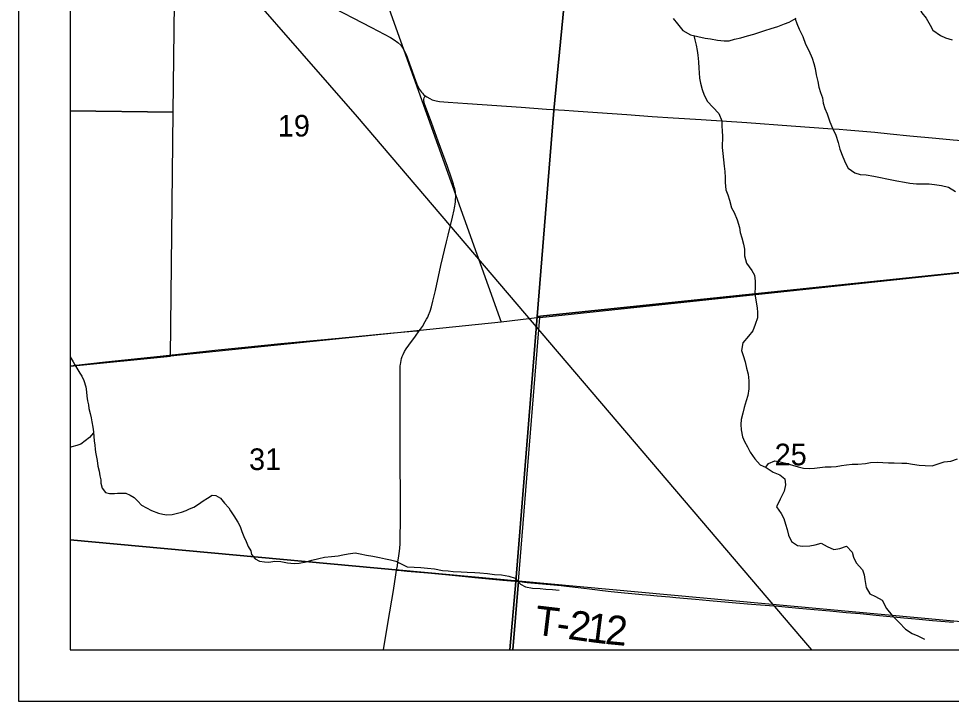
# Model space of a CAD drawing. Extents: x 0 to 34, y -5.4 to 22.
# Drawn here: x 2 to 3.809, y 14 to 15.324 of the extents above; entities that cross this region are included whole.
import ezdxf

# ---------------------------------------------------------------- set-up
doc = ezdxf.new("R2010")
doc.units = 0
for name, color, linetype in [('Default', 7, 'Continuous'), ('GM_X_County_Road', 7, 'Continuous'), ('GM_X_Minor_River', 7, 'Continuous'), ('GM_X_Rail_Line', 7, 'Continuous'), ('GM_X_Section', 7, 'Continuous'), ('GM_X_Section_Text', 7, 'Continuous'), ('GM_X_Township_Road', 7, 'Continuous'), ('GM_X_Township_Road_Text', 7, 'Continuous'), ('SH_Data', 7, 'Continuous')]:
    doc.layers.add(name, color=color, linetype=linetype)

msp = doc.modelspace()

# ---------------------------------------------------------------- linework, layer by layer
at = {"layer": 'Default'}
for points in [[(2.1, 16.1508), (2.1, 15.1447), (2.2999, 15.1427), (2.3117, 16.1481)], [(2.1, 15.1447), (2.1, 14.6497), (2.2946, 14.6693), (2.2999, 15.1427)], [(2.1, 14.6497), (2.1, 14.3134), (2.9696, 14.2333), (3.0111, 14.744), (2.936, 14.7352), (2.2946, 14.6693)], [(2.1, 14.3134), (2.1, 14.1), (2.9585, 14.1), (2.9696, 14.2333)], [(2.9585, 14.1), (3.9718, 14.1), (3.9753, 14.1377), (3.9754, 14.1403), (2.9696, 14.2333)]]:
    msp.add_lwpolyline(points, close=True, dxfattribs=at)
at = {"layer": 'GM_X_County_Road'}
for points in [[(2.5943, 15.3533), (2.6843, 15.3064), (2.7211, 15.2873), (2.7285, 15.2828), (2.7356, 15.2775), (2.741, 15.2721), (2.745, 15.2668), (2.7485, 15.2607), (2.7514, 15.2544), (2.7697, 15.2036), (2.7722, 15.1969), (2.7747, 15.1916), (2.7774, 15.1863), (2.7811, 15.1811), (2.7831, 15.179), (2.7853, 15.1769), (2.7887, 15.1742), (2.7919, 15.172), (2.7974, 15.1687), (2.802, 15.1665), (2.8046, 15.1656), (2.8073, 15.1648), (2.8101, 15.1642), (2.8128, 15.1638), (2.8163, 15.1633), (2.8331, 15.1616), (2.8703, 15.1589), (2.9744, 15.1519), (3.024, 15.1485), (3.0588, 15.1461)], [(3.0588, 15.1461), (3.0761, 15.1449), (3.1226, 15.1417), (3.1796, 15.1377), (3.2286, 15.1343), (3.2695, 15.1315), (3.3241, 15.1279), (3.4127, 15.1221), (3.4983, 15.1162), (3.5785, 15.1102), (3.5913, 15.1092), (3.6065, 15.1081), (3.6608, 15.1033), (3.6903, 15.1005), (3.7286, 15.0967), (3.7787, 15.0919), (3.8127, 15.0888), (3.8542, 15.0853), (3.892, 15.0828), (3.9472, 15.0791), (3.9927, 15.0764), (4.065, 15.0719), (4.0712, 15.0715)]]:
    msp.add_lwpolyline(points, dxfattribs=at)
at = {"layer": 'GM_X_Minor_River'}
for points in [[(3.6771, 15.4213), (3.6791, 15.4103), (3.6831, 15.3981), (3.698, 15.3891), (3.7082, 15.3848), (3.7183, 15.3782), (3.7292, 15.3708), (3.7395, 15.3566), (3.7447, 15.347), (3.7516, 15.3348), (3.7602, 15.3247), (3.7683, 15.311), (3.773, 15.3014), (3.788, 15.2909), (3.7978, 15.2866), (3.8109, 15.2825)], [(3.2697, 15.324), (3.2779, 15.3136), (3.2883, 15.3009), (3.3029, 15.2923), (3.3172, 15.2891), (3.3319, 15.2861), (3.3421, 15.2848), (3.3553, 15.2823), (3.3685, 15.2806), (3.3784, 15.2808), (3.3882, 15.2837), (3.4008, 15.2865), (3.4137, 15.2904), (3.4263, 15.2936), (3.4377, 15.2972), (3.4472, 15.3005), (3.4597, 15.3044), (3.4727, 15.3088), (3.4853, 15.3139), (3.4948, 15.3171), (3.5081, 15.3245)], [(3.5062, 15.3234), (3.5091, 15.3142), (3.5142, 15.3035), (3.5208, 15.289), (3.5262, 15.2745), (3.5324, 15.2622), (3.539, 15.2473), (3.5426, 15.2367), (3.5451, 15.2271), (3.5472, 15.2146), (3.55, 15.2016), (3.5524, 15.191), (3.5553, 15.1807), (3.5589, 15.17), (3.5606, 15.1601), (3.5639, 15.1498), (3.5682, 15.1391), (3.5737, 15.1239), (3.5787, 15.1116), (3.5849, 15.0979), (3.5896, 15.0838), (3.5928, 15.0708), (3.5986, 15.0555), (3.6041, 15.0437), (3.6089, 15.0341), (3.6216, 15.0248), (3.6325, 15.0216), (3.6438, 15.0206), (3.6585, 15.0181), (3.6717, 15.016), (3.6838, 15.0131), (3.6936, 15.0111), (3.7034, 15.0094), (3.7181, 15.0065), (3.7287, 15.0048), (3.7415, 15.0034), (3.7552, 15.0036), (3.7661, 15.0034), (3.7767, 15.0024), (3.7903, 14.9999), (3.8035, 14.9967), (3.817, 14.9885)], [(3.3097, 15.2908), (3.3118, 15.2827), (3.3143, 15.2724), (3.3164, 15.2621), (3.3177, 15.2526), (3.3186, 15.2401), (3.3192, 15.228), (3.3198, 15.2185), (3.3208, 15.2082), (3.3225, 15.1987), (3.3261, 15.1861), (3.3297, 15.1754), (3.3363, 15.1632), (3.3463, 15.152), (3.3582, 15.14), (3.3637, 15.1255), (3.3639, 15.1157), (3.3648, 15.1058), (3.365, 15.0959), (3.3647, 15.0736), (3.3656, 15.0625), (3.3673, 15.05), (3.3686, 15.0378), (3.37, 15.0272), (3.3701, 15.0158), (3.3704, 15.006), (3.372, 14.9919), (3.3756, 14.982), (3.3789, 14.972), (3.3828, 14.9572), (3.3879, 14.9476), (3.3937, 14.9335), (3.3984, 14.9186), (3.3998, 14.9091), (3.4026, 14.8984), (3.4062, 14.8866), (3.4079, 14.8767), (3.4081, 14.8635), (3.412, 14.8494), (3.422, 14.8355), (3.4271, 14.826), (3.4285, 14.8149), (3.4283, 14.8043), (3.4277, 14.7903), (3.4301, 14.7781), (3.4325, 14.7633), (3.4331, 14.7538), (3.4333, 14.7439), (3.4286, 14.7307), (3.4238, 14.7183), (3.4157, 14.7082), (3.4045, 14.6951), (3.402, 14.6804), (3.4056, 14.6708), (3.4095, 14.6582), (3.412, 14.6457), (3.4148, 14.6346), (3.4165, 14.6213), (3.4166, 14.6058), (3.4141, 14.5933), (3.4109, 14.5827), (3.4073, 14.5695), (3.4045, 14.5586), (3.4016, 14.5465), (3.4007, 14.5367), (3.4013, 14.5264), (3.4041, 14.5131), (3.4077, 14.5035), (3.414, 14.4932), (3.4191, 14.4832), (3.428, 14.4702), (3.4384, 14.4586), (3.45, 14.4535), (3.4635, 14.4442), (3.4763, 14.4394), (3.4863, 14.4316), (3.4873, 14.4199), (3.4848, 14.4074), (3.477, 14.392), (3.4699, 14.3773), (3.4788, 14.3639), (3.4843, 14.3543), (3.4871, 14.3433), (3.4908, 14.3333), (3.4932, 14.3223), (3.4991, 14.3101), (3.5107, 14.3019), (3.5212, 14.301), (3.5345, 14.3015), (3.5447, 14.3036), (3.5569, 14.3068), (3.5682, 14.3005), (3.5813, 14.2946), (3.5927, 14.296), (3.6056, 14.301), (3.6168, 14.2891), (3.6196, 14.2796), (3.6248, 14.2685), (3.6366, 14.255), (3.6403, 14.2455), (3.6416, 14.236)], [(2.1, 14.6682), (2.1058, 14.6581), (2.1091, 14.6523), (2.1186, 14.6362), (2.1227, 14.6305), (2.1263, 14.6221), (2.1303, 14.6095), (2.1313, 14.6004), (2.1323, 14.592), (2.1336, 14.5825), (2.1354, 14.5749), (2.1364, 14.5677), (2.1389, 14.5582), (2.1406, 14.5498), (2.142, 14.5418), (2.1437, 14.5315), (2.1451, 14.5228), (2.146, 14.5133), (2.1466, 14.5049), (2.1476, 14.4966), (2.1483, 14.489), (2.1493, 14.4833), (2.1503, 14.4764), (2.1524, 14.4669), (2.1534, 14.4559), (2.1559, 14.4464), (2.1572, 14.4373), (2.1593, 14.4293), (2.1596, 14.4232), (2.1621, 14.4133), (2.1684, 14.4052), (2.1763, 14.4032), (2.1858, 14.403), (2.1915, 14.4037), (2.2006, 14.4039), (2.2078, 14.4034), (2.2164, 14.3995), (2.2239, 14.3955), (2.2313, 14.3878), (2.238, 14.3805), (2.2482, 14.375), (2.2576, 14.3703), (2.2715, 14.3648), (2.2798, 14.3631), (2.2877, 14.3618), (2.2976, 14.362), (2.3056, 14.3642), (2.3158, 14.367), (2.325, 14.3703), (2.3311, 14.3732)], [(2.1453, 14.5203), (2.1377, 14.5115), (2.1208, 14.4989), (2.1128, 14.4961), (2.1029, 14.4932), (2.1, 14.4919)], [(3.4494, 14.4538), (3.4543, 14.4614), (3.4669, 14.4665), (3.4771, 14.4644), (3.4872, 14.4616), (3.5012, 14.4576), (3.5121, 14.4547), (3.5226, 14.4519), (3.5336, 14.4517), (3.5438, 14.4523), (3.5537, 14.4536), (3.5643, 14.4546), (3.576, 14.4544), (3.5859, 14.455), (3.5961, 14.4571), (3.606, 14.4588), (3.617, 14.4598), (3.628, 14.4599), (3.6424, 14.4612), (3.6526, 14.4633), (3.6659, 14.4639), (3.6761, 14.4629), (3.6874, 14.4623), (3.698, 14.4622), (3.7128, 14.4615), (3.7226, 14.4617), (3.7336, 14.46), (3.7468, 14.4579), (3.7585, 14.4573), (3.7717, 14.4564), (3.7816, 14.46), (3.7953, 14.4643), (3.8082, 14.4656), (3.8208, 14.4699)], [(2.3311, 14.3732), (2.3399, 14.3765), (2.349, 14.382), (2.3579, 14.3887), (2.3663, 14.3938), (2.3751, 14.3997), (2.3827, 14.3992), (2.3917, 14.3941), (2.3991, 14.3845), (2.4076, 14.3749), (2.4109, 14.3692), (2.4176, 14.3596), (2.4253, 14.3477), (2.4294, 14.3393), (2.433, 14.3293), (2.4366, 14.3198), (2.441, 14.3102), (2.445, 14.3003), (2.4501, 14.2919), (2.4515, 14.285), (2.459, 14.2766), (2.4672, 14.2719), (2.4766, 14.2702), (2.4852, 14.2699), (2.4971, 14.2718)], [(2.4971, 14.2718), (2.5088, 14.2709), (2.5213, 14.2688), (2.5345, 14.2674), (2.5443, 14.2676), (2.558, 14.2704), (2.5686, 14.274), (2.5823, 14.2772), (2.5933, 14.2793), (2.607, 14.2806), (2.6195, 14.2823), (2.629, 14.284), (2.6389, 14.2857), (2.6529, 14.2878), (2.6627, 14.2861), (2.6744, 14.2836), (2.6868, 14.2815), (2.6997, 14.2786), (2.7113, 14.2761), (2.7215, 14.2745), (2.7313, 14.272), (2.7433, 14.2657), (2.7535, 14.261), (2.7671, 14.26), (2.7799, 14.2594), (2.7928, 14.2581), (2.8068, 14.2567), (2.8218, 14.2534), (2.8328, 14.2528), (2.8426, 14.2519), (2.8581, 14.2509), (2.8702, 14.2503), (2.885, 14.2497), (2.8948, 14.2491), (2.9092, 14.2481), (2.9228, 14.246), (2.9364, 14.2454), (2.9511, 14.2428), (2.9631, 14.2385), (2.9732, 14.2273), (2.9829, 14.2218), (2.9969, 14.2197), (3.0116, 14.2187), (3.0226, 14.2177), (3.0354, 14.2167), (3.0487, 14.2158)], [(3.6416, 14.236), (3.644, 14.2207), (3.651, 14.2085), (3.6619, 14.2034), (3.675, 14.1959), (3.6834, 14.1799), (3.6942, 14.1664), (3.7076, 14.1529), (3.7199, 14.1402), (3.733, 14.1312), (3.7439, 14.1269), (3.757, 14.1202)]]:
    msp.add_lwpolyline(points, dxfattribs=at)
at = {"layer": 'GM_X_Rail_Line'}
for points in [[(2.1, 20.2033), (2.1, 14.1), (2.9527, 14.1), (2.9641, 14.2324), (3.0059, 14.7462), (3.0382, 15.1455), (3.0967, 15.7517), (3.13, 16.1326), (3.2432, 17.2942), (3.3599, 18.5136), (3.3607, 18.5226), (3.3669, 18.5872), (3.3865, 18.7781), (3.4297, 19.2264), (3.4301, 19.2311), (3.4303, 19.2337), (3.46, 19.8188), (3.4778, 20.1697), (3.2417, 20.1756), (2.1537, 20.2026)], [(2.9527, 14.1), (8.0559, 14.1), (8.0925, 14.4946), (8.0933, 14.5029), (8.1066, 14.6429), (8.1702, 15.3079), (7.8983, 15.2739), (7.8942, 15.2734), (7.6929, 15.2483), (7.6796, 15.247), (7.3134, 15.2082), (7.0389, 15.1799), (6.9914, 15.1749), (6.9348, 15.169), (6.9294, 15.1684), (6.92, 15.1674), (6.4463, 15.1177), (6.4403, 15.1171), (6.1164, 15.0793), (4.8765, 14.9444), (4.7395, 14.9295), (4.0439, 14.8538), (3.0059, 14.7462), (2.9641, 14.2324)]]:
    msp.add_lwpolyline(points, close=True, dxfattribs=at)
for points in [[(3.2432, 17.2942), (3.13, 16.1326), (3.0967, 15.7517), (3.0382, 15.1455), (3.0059, 14.7462), (4.0439, 14.8538), (4.7395, 14.9295)], [(2.1, 16.2102), (2.1109, 16.1503), (2.1533, 15.9186), (2.1742, 15.7991), (2.1915, 15.7268), (2.2211, 15.6634), (2.254, 15.6096), (2.2936, 15.5559), (2.3392, 15.4972), (2.6567, 15.1332), (3.5187, 14.1225), (3.5377, 14.1)]]:
    msp.add_lwpolyline(points, dxfattribs=at)
at = {"layer": 'GM_X_Section'}
for points in [[(2.3117, 16.1481), (3.3134, 16.1326), (3.3056, 15.7771), (2.5957, 15.6862), (2.936, 14.7352), (2.2946, 14.6693), (2.2999, 15.1427)], [(4.0448, 14.8547), (3.9754, 14.1403), (2.9696, 14.2333), (3.0111, 14.744), (3.928, 14.842)]]:
    msp.add_lwpolyline(points, close=True, dxfattribs=at)
at = {"layer": 'GM_X_Township_Road'}
msp.add_line((2.9622, 14.233), (2.9713, 14.2321), dxfattribs=at)
for points in [[(2.7076, 14.1), (2.7167, 14.1548), (2.7268, 14.2149), (2.7317, 14.2451), (2.7332, 14.2544), (2.7346, 14.2626), (2.7358, 14.27), (2.7375, 14.282), (2.7388, 14.2913), (2.7393, 14.2969), (2.7395, 14.2997), (2.7397, 14.3029), (2.7399, 14.3073), (2.7403, 14.3167), (2.7408, 14.3497), (2.7407, 14.3907), (2.7402, 14.4702), (2.7402, 14.5467), (2.7397, 14.5995), (2.7398, 14.6212), (2.7398, 14.6306), (2.7398, 14.6363), (2.74, 14.6438), (2.7402, 14.648), (2.7403, 14.6503), (2.7406, 14.6533), (2.741, 14.6568), (2.7418, 14.6606), (2.7428, 14.6648), (2.7441, 14.6686), (2.7457, 14.6723), (2.7487, 14.6783), (2.7519, 14.6835), (2.7569, 14.6906), (2.7697, 14.7078), (2.7771, 14.7182), (2.7794, 14.7215), (2.7831, 14.7269), (2.7887, 14.7363), (2.7912, 14.7408), (2.7935, 14.7447), (2.7951, 14.7485), (2.7982, 14.7565), (2.8007, 14.7649), (2.8035, 14.7756), (2.8083, 14.7968), (2.819, 14.8452), (2.8298, 14.8907), (2.8331, 14.9039), (2.8416, 14.9388), (2.8447, 14.9527), (2.8455, 14.9571), (2.846, 14.9599), (2.8466, 14.964), (2.8472, 14.9683), (2.8474, 14.9709), (2.8476, 14.9734), (2.8478, 14.9777), (2.8477, 14.9805), (2.8475, 14.9843), (2.8472, 14.9878), (2.8466, 14.9908), (2.8458, 14.9938), (2.8449, 14.9978), (2.8433, 15.0029), (2.8397, 15.0142), (2.8316, 15.0371), (2.8136, 15.0861), (2.8006, 15.1223), (2.7875, 15.1587), (2.7864, 15.1616), (2.786, 15.1636), (2.7857, 15.1655), (2.7859, 15.1678), (2.7868, 15.1704), (2.7887, 15.1742)], [(2.1, 14.6508), (2.1056, 14.6513), (2.1684, 14.6581), (2.2746, 14.6691), (2.3807, 14.6807), (2.4323, 14.686), (2.5085, 14.6936), (2.6212, 14.7044), (2.7197, 14.7136), (2.7637, 14.7176), (2.7726, 14.7182), (2.7771, 14.7182)], [(2.7332, 14.2544), (2.7349, 14.2542), (2.7417, 14.2536), (2.7534, 14.2525), (2.7936, 14.2489), (2.8277, 14.2458), (2.8605, 14.2425), (2.8846, 14.2404), (2.9391, 14.2352), (2.9622, 14.233)], [(2.9713, 14.2321), (2.9861, 14.2306), (3.0383, 14.226), (3.0523, 14.2248), (3.0628, 14.2236), (3.0851, 14.221), (3.0963, 14.2196), (3.1071, 14.218), (3.1178, 14.2165), (3.1324, 14.2147), (3.1491, 14.2129), (3.175, 14.2102), (3.1892, 14.2092), (3.2094, 14.2074), (3.2256, 14.2059), (3.2383, 14.2045), (3.2633, 14.2023), (3.2748, 14.2014), (3.2974, 14.1992), (3.313, 14.198), (3.3401, 14.1954), (3.3768, 14.1923), (3.3911, 14.1911), (3.4214, 14.1885), (3.4741, 14.1844), (3.4869, 14.183), (3.513, 14.1804), (3.5429, 14.1779), (3.5736, 14.1755), (3.605, 14.1725), (3.6323, 14.17), (3.6632, 14.167), (3.7171, 14.1621), (3.747, 14.1592), (3.7723, 14.157), (3.8133, 14.1534)]]:
    msp.add_lwpolyline(points, dxfattribs=at)
at = {"layer": 'SH_Data'}
for p, q in [((2, 21), (2, 14)), ((2.1, 20.9), (2.1, 14.1)), ((2.1, 14.1), (8.9, 14.1)), ((2.1, 14.1), (2.1, 14.1)), ((2, 14), (9, 14))]:
    msp.add_line(p, q, dxfattribs=at)

# ---------------------------------------------------------------- texts
at = {"layer": 'GM_X_Section_Text'}
for s, p in [('19', (2.5027, 15.0952)), ('31', (2.4469, 14.4485)), ('25', (3.4664, 14.4577))]:
    msp.add_text(s, height=0.04186, rotation=0, dxfattribs=at).set_placement(p)
at = {"layer": 'GM_X_Township_Road_Text'}
for s, rotation, p in [('T', 353.1998, (2.9988, 14.1296)), ('2', 351.697, (3.0637, 14.1213)), ('1', 352.7319, (3.0995, 14.1161)), ('2', 354.4806, (3.1361, 14.1115)), ('-', 351.8622, (3.0407, 14.1246))]:
    msp.add_text(s, height=0.0568, rotation=rotation, dxfattribs=at).set_placement(p)

doc.saveas('drawing.dxf')
